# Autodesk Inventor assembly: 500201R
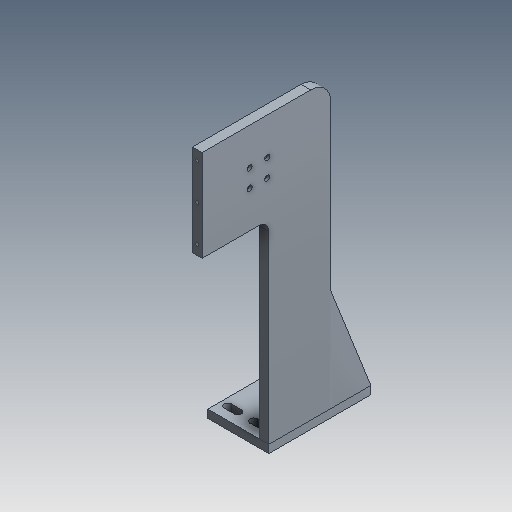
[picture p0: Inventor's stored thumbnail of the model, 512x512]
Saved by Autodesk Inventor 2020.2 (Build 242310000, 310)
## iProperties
Created: 1999-11
Part Number: 500201R
Description: WMT-CP,SA,XX,ARM,VACUUM_CUP
Document SubType Name: Assembly
Designer: sspink
Mass: 1640.92 g
Surface Area: 1292.4 cm^2
Volume: 605.504 cm^3
Density: 2.71 g/cm^3
Control State: 0
Checked Out: False
Last Check In By: sspink
Last Check In Date: 1999-12-22
Master: False
Shininess: 0.0
Length Units: 11272
Angle Units: 11279
Time Units: 11290
Mass Units: 11286
Length Display Precision: 3
Angle Display Precision: 2
Compacted: True
Dimensions: 14,4x8,3x3 in
Mass: 3,618 lb
DocNumber: 500201R.iam
Folder: 01 - Themengebiete\Simplification\01 - Packaging machine\
VDS_Category: 3D Komponenten
Density: 0.0
Volumn: 0.0
Area: 0.0
PropertySet Name: Model Information
Author: sspink
Revision Number: -
Title: plate
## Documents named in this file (4)
- D:\07 - DEMODATEN\OTX 2019 - Dataset - UPDATE - Dez2019\Designs\07-Packing machine\500201R.iam
- D:\07 - DEMODATEN\OTX 2019 - Dataset - UPDATE - Dez2019\Designs\07-Packing machine\Parts\ADSK-011296.ipt
- D:\07 - DEMODATEN\OTX 2019 - Dataset - UPDATE - Dez2019\Designs\07-Packing machine\Parts\ADSK-011297.ipt
- D:\07 - DEMODATEN\OTX 2019 - Dataset - UPDATE - Dez2019\Designs\07-Packing machine\Parts\ADSK-011299.ipt
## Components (3 placed, 3 different names)
1. ADSK-011296:1 — Passend:1, Fluchtend:1, Fluchtend:2, Passend:2, Fluchtend:3
2. ADSK-011297:1 — Passend:2, Passend:3, Fluchtend:3
3. ADSK-011299:1 — Passend:1, Fluchtend:1, Fluchtend:2, Passend:3
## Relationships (6: Mate 3, Flush 3)
- Passend:1 [Mate]: ADSK-011296:1 ↔ ADSK-011299:1
- Fluchtend:1 [Flush]: ADSK-011296:1 ↔ ADSK-011299:1
- Fluchtend:2 [Flush]: ADSK-011296:1 ↔ ADSK-011299:1
- Passend:2 [Mate]: ADSK-011296:1 ↔ ADSK-011297:1
- Passend:3 [Mate]: ADSK-011297:1 ↔ ADSK-011299:1
- Fluchtend:3 [Flush]: ADSK-011296:1 ↔ ADSK-011297:1
